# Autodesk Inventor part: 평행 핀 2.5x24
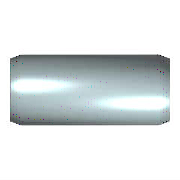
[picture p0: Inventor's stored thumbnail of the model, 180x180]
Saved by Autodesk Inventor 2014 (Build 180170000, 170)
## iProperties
IsCustomPart: 1
Created: 2012-02
Part Number: 평행 핀 2.5x24
Material: 강철, 연강
Description: 평행 핀
Document SubType Name: Modeling
Standard: KS B 1320
Designer: mduedu
Standards Organization: KS
Language: ko-KR
Size Designation: B 2.5 x  24
Categories: <MemberInstance><Categories><Category DisplayName="조임쇠" InternalName="e4da775c-781d-43d5-af7c-5136215cf5a6" Mnemonic="FSTN"><Category DisplayName="핀" InternalNa
Density: 1 g/cm^3
Appearance: Yellow
Author: mduedu
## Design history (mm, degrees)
sketch "스케치"
  geometry: C1 r 1.25 at (0, 0); 1 further point
  constraints: 1 centre point, 1 coincident
  dimensions: "d1" = 2.5 diameter of C1 (= NND)
extrude "본체" new body sketch "스케치" distance "d2" = 24 (= NLG); taper "d3" = 0 deg
chamfer "스케치2" distance "d8" = 0.4 (= PHH); stored, may be unused: angle "d9" = 15 deg (= FAWI), second distance "d12" = 0.4 (= PHH)
node "작업 평면1"
body "Solid1"
chamfer "모따기1" distance "d4" = 0.4 (= PHH); stored, may be unused: angle "d5" = 15 deg (= FAWI), second distance "d11" = 0.4 (= PHH)
other parameters: "NND" = 2.5 [user parameter; used in 1 equation term], "NLG" = 24 [user parameter; used in 1 equation term], "PHH" = 0.4 [user parameter; used in 4 equation terms], "FAWI" = 15 deg [user parameter; used in 2 equation terms], "d13" = 0, "d15" = 0, "d16" = 0, "KAH" = 0.3 [user parameter]
